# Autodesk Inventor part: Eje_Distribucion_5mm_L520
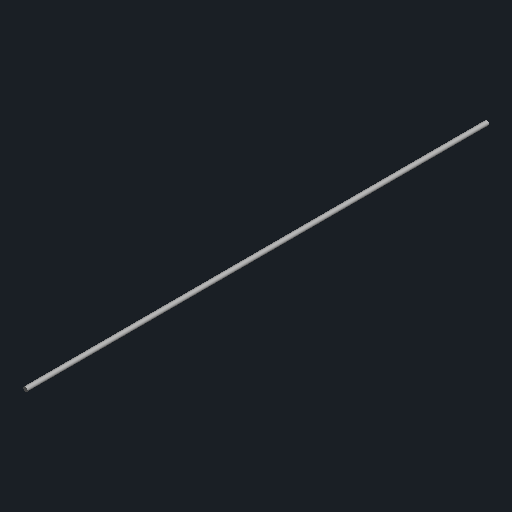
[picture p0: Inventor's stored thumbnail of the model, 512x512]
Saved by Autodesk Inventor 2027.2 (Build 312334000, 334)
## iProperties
Part Number: Eje_Distribucion_5mm_L520
Material: Genérico
Document SubType Name: Modelado
Designer: Usuario
Appearance: Por defecto
Author: Usuario
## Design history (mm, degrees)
sketch "Boceto1"
  geometry: C1 r 2.5 at (0, 0)
  constraints: 1 centre point
  dimensions: "d0" = 520 dimension on C1.centre C1
extrude "Extrusión1" new body sketch "Boceto1" stored distance "d0" = 520; taper "d1" = 0 deg
node "Sólido1"
node "Cuerpos sólidos"
node "Cuerpos de superficie"
